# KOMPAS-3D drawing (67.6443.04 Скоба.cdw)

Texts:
  Скоба
  *Размер для справок.
  Длина развертки L=140 мм.
  Шероховатость поверхностей реза  6,3 .
  Нач. КО
Dimensions and other numbers on the sheet: 55; 10; 27; 30; 5,5; 5; 2; 15; 3; 4; 1:1; 1; 0,059; 0; 6; 7; 8; 9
